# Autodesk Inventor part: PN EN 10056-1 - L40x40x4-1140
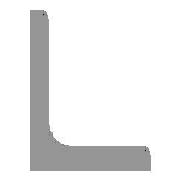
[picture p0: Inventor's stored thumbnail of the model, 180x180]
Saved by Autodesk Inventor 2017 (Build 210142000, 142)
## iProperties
IsCustomPart: 1
Created: 2020-07
Part Number: PN EN 10056-1 - L40x40x4-1140
Material: Stal, miękka
Description: Kątownik równoramienny
Document SubType Name: Modeling
Standard: PN
Designer: X
Standards Organization: PN
Language: pl-PL
Size Designation: L40x40x4
Categories: <MemberInstance><Categories><Category DisplayName="Kształtowniki konstrukcyjne" InternalName="089c4875-fa83-4c05-b084-43b9cc11f5ed" Mnemonic="GRDR"><CategoryPar
Stock Number: L40x40x4
Density: 7.85 g/cm^3
Appearance: Częściowo polerowana
_CCFamilyMember: 70
_CCFamilyDisplayName: PN EN 10056-1 (Kątownik równoramienny) - Kątownik równoramienny
_FrameMemberDoc: Frame Member File
_Version: 15.0.0
_GetPNFromCC: 1
G_L: 1140,000 mm
G_W: 40,000 mm
G_H: 40,000 mm
Author: X
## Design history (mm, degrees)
node "Płaszczyzna początkowa"
node "Płaszczyzna końcowa"
sketch "Szkic2"
  geometry: L1 (-7.249, -1.249)-(-7.249, 25.751); L2 (-11.249, 28.751)-(-10.249, 28.751); L3 (-11.249, -11.249)-(-11.249, 28.751); L4 (-11.249, -11.249)-(28.751, -11.249); L5 (28.751, -10.249)-(28.751, -11.249); L6 (-1.249, -7.249)-(25.751, -7.249); L7 (0, 37.497)-(0, -19.373) reference; L8 (-19.373, 0)-(37.497, 0) reference; A1 r 6 centre (-1.249, -1.249) between (-7.249, -1.249) and (-1.249, -7.249); A2 r 3 centre (-10.249, 25.751) between (-7.249, 25.751) and (-10.249, 28.751); A3 r 3 centre (25.751, -10.249) between (28.751, -10.249) and (25.751, -7.249); 3 further points
  constraints: 12 end point, 6 point on circle, 6 point on line, 6 tangent, 3 centre point, 3 horizontal, 3 vertical, 1 equal radius
  dimensions: "d4" = 40 distance of L3.start L4.end (= b); "d6" = 40 distance of L3.start L2.start (= b); "d8" = 4 distance of point (28.751, -7.249) L4.end (= ParT); "d10" = 4 distance of L2.start point (-7.249, 28.751) (= ParT); "d17" = 6 radius of A1 (= R); "d18" = 3 radius of A2 (= R1); "d19" = 11.24871 distance between parallel lines of L8 L4 (= ex); "d20" = 11.24871 distance between parallel lines of L3 L7 (= d19)
extrude "Bryła" new body sketch "Szkic2" stored distance "d11" = 1140 (= G_L); taper "d12" = 0 deg
node "Driven Length"
  sketch "Sketch3"
    geometry: L1 (0, 0)-(10, 0) reference
    constraints: 2 end point, 1 horizontal
  workplane "Work Plane10"
  sketch "Sketch4"
    geometry: L1 (-2, 0)-(12, 0) reference; L2 (-2, 1140)-(12, 1140) reference
    dimensions: "d24" = 1140 distance between parallel lines of L1 L2 (derived)
body "Solid1"
other parameters: "b" = 40 [user parameter; used in 3 equation terms], "ParT" = 4 [user parameter; used in 3 equation terms], "R" = 6 [user parameter; used in 1 equation term], "R1" = 3 [user parameter; used in 1 equation term], "G_L" = 1140 (= d24) [user parameter; used in 1 equation term], "d7" = 4 (derived), "d9" = 4 (derived), "ex" = 11.24871 (computed from b, ParT) [user parameter; used in 1 equation term], "G_OFFSET_START" = 0 [user parameter; used in 1 equation term], "G_OFFSET_END" = 0 [user parameter; used in 1 equation term], "d21" = 0 (computed from G_OFFSET_START), "d23" = 90 deg
